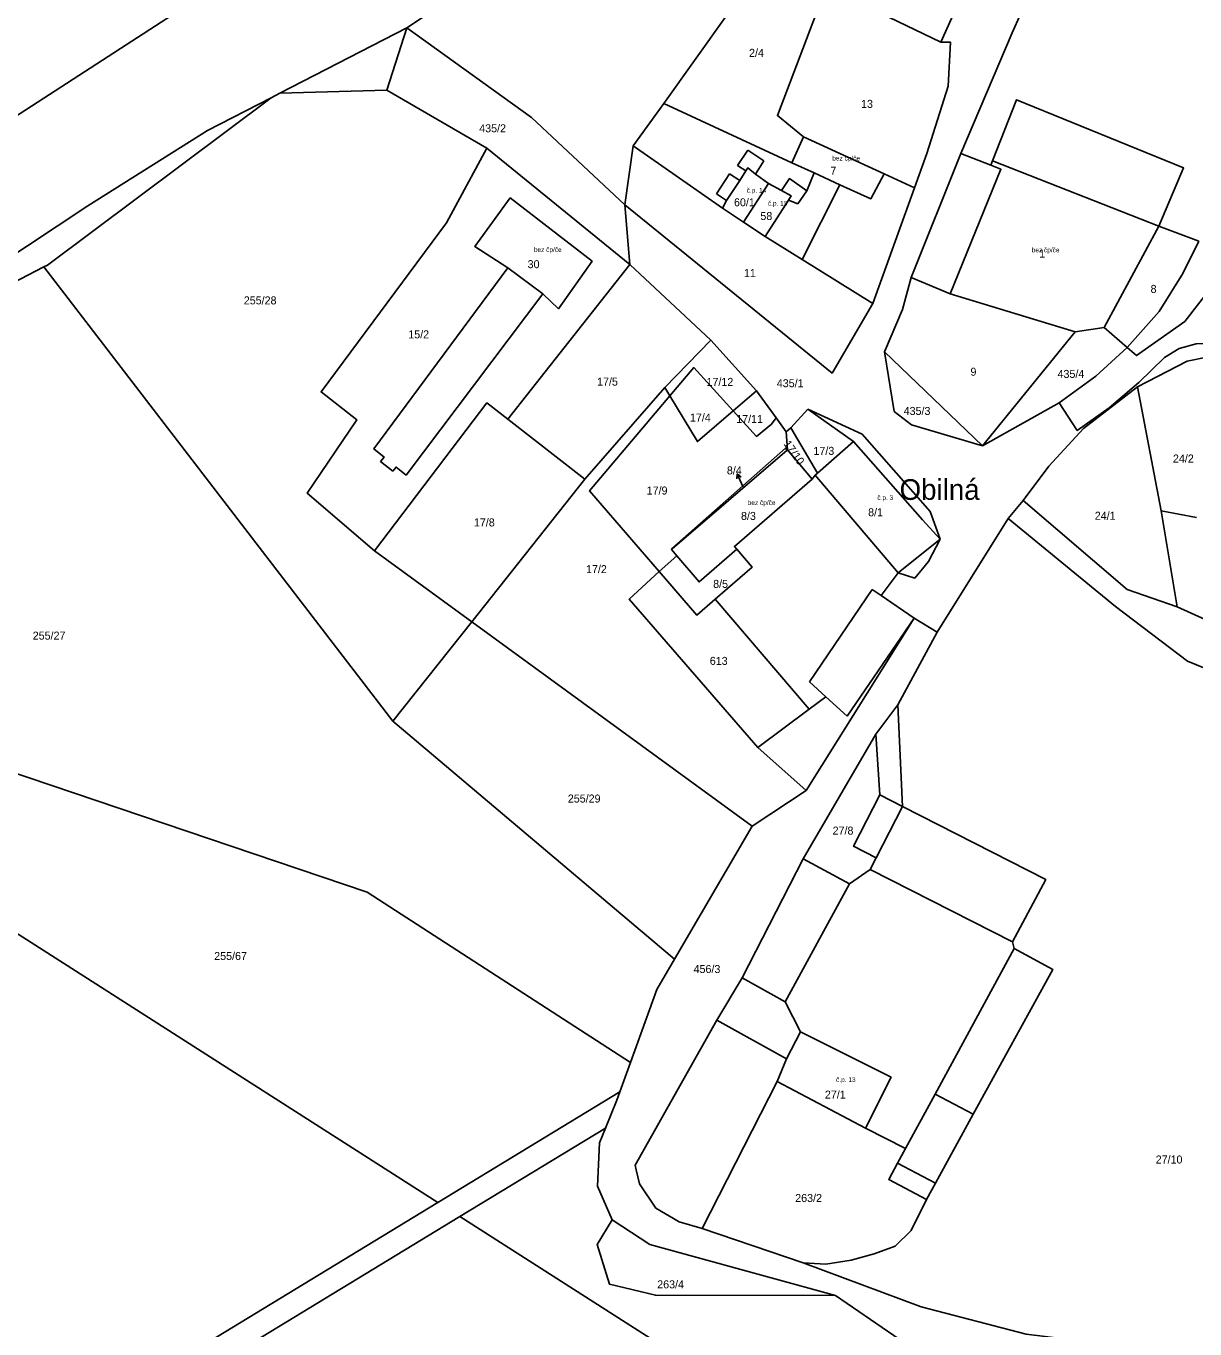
# Model space of a CAD drawing. Extents: x -887272 to -877616, y -1026687 to -1019819.
# Drawn here: x -880738 to -880489.6, y -1021447 to -1021170.2 of the extents above; entities that cross this region are included whole.
import ezdxf

# ---------------------------------------------------------------- set-up
doc = ezdxf.new("R2010")
doc.units = 0
for name, color, linetype in [('Definiční body', 7, 'Continuous'), ('Hranice parcel', 7, 'Continuous'), ('Parcelní čísla', 7, 'Continuous'), ('Polygon budovy', 7, 'Continuous'), ('Pop  PČ popisy', 7, 'Continuous'), ('Vnitřní kresba', 7, 'Continuous')]:
    doc.layers.add(name, color=color, linetype=linetype)

msp = doc.modelspace()

# ---------------------------------------------------------------- linework, layer by layer
at = {"layer": 'Hranice parcel'}
for p, q in [((-880602.77, -1021134.34), (-880657.13, -1021170.56)), ((-880661.35, -1021183.81), (-880657.13, -1021170.56)), ((-880684.13, -1021184.49), (-880685.95, -1021185.43)), ((-880661.35, -1021183.81), (-880684.13, -1021184.49)), ((-880640.11, -1021196.16), (-880661.35, -1021183.81)), ((-880602.45, -1021186.68), (-880609.03, -1021195.67)), ((-880575.27, -1021199.23), (-880602.45, -1021186.68)), ((-880610.78, -1021208.19), (-880609.03, -1021195.67)), ((-880572.81, -1021193.74), (-880575.27, -1021199.23)), ((-880609.7, -1021220.83), (-880640.11, -1021196.16)), ((-880539.35, -1021197.25), (-880549.94, -1021223.64)), ((-880575.27, -1021199.23), (-880570.51, -1021201.41)), ((-880558.09, -1021229.15), (-880549.21, -1021204.6)), ((-880610.78, -1021208.19), (-880609.7, -1021220.83)), ((-880508.88, -1021234.25), (-880497.26, -1021212.75)), ((-880497.26, -1021212.75), (-880488.78, -1021215.92)), ((-880635.66, -1021253.7), (-880609.7, -1021220.83)), ((-880592.5, -1021236.92), (-880609.7, -1021220.83)), ((-880573.11, -1021219.79), (-880558.09, -1021229.15)), ((-880660.06, -1021317.87), (-880734.24, -1021221.36)), ((-880515.07, -1021235.18), (-880508.88, -1021234.25)), ((-880508.88, -1021234.25), (-880503.97, -1021238.53)), ((-880602.26, -1021246.99), (-880592.5, -1021236.92)), ((-880592.5, -1021236.92), (-880582.78, -1021247.68)), ((-880534.73, -1021259.38), (-880515.07, -1021235.18)), ((-880555.55, -1021239.39), (-880534.73, -1021259.38)), ((-880553.51, -1021252.07), (-880555.55, -1021239.39)), ((-880602.26, -1021246.99), (-880619.24, -1021266.45)), ((-880601.19, -1021248.78), (-880602.26, -1021246.99)), ((-880582.78, -1021247.68), (-880587.74, -1021251.95)), ((-880582.78, -1021247.68), (-880578.62, -1021253.43)), ((-880496.75, -1021273.23), (-880501.78, -1021246.86)), ((-880518.44, -1021250.25), (-880534.73, -1021259.38)), ((-880635.66, -1021253.7), (-880619.24, -1021266.45)), ((-880578.62, -1021253.43), (-880576.45, -1021256.43)), ((-880571.85, -1021251.6), (-880575.52, -1021255.6)), ((-880549.81, -1021254.92), (-880553.51, -1021252.07)), ((-880576.45, -1021256.43), (-880575.52, -1021255.6)), ((-880576.21, -1021260.26), (-880576.45, -1021256.43)), ((-880575.52, -1021255.6), (-880569.82, -1021265.22)), ((-880534.73, -1021259.38), (-880549.81, -1021254.92)), ((-880576.27, -1021260.3), (-880600.72, -1021281.3)), ((-880576.21, -1021260.26), (-880576.27, -1021260.3)), ((-880570.93, -1021266.47), (-880576.21, -1021260.26)), ((-880619.24, -1021266.45), (-880643.31, -1021296.77)), ((-880570.93, -1021266.47), (-880587.47, -1021280.76)), ((-880526.13, -1021271.04), (-880529.31, -1021274.86)), ((-880493.37, -1021293.62), (-880496.75, -1021273.23)), ((-880496.75, -1021273.23), (-880489.23, -1021274.65)), ((-880529.31, -1021274.86), (-880544.36, -1021298.96)), ((-880663.97, -1021281.71), (-880643.31, -1021296.77)), ((-880587.47, -1021280.76), (-880586.95, -1021281.37)), ((-880599.75, -1021282.74), (-880603.45, -1021286.13)), ((-880660.06, -1021317.87), (-880643.31, -1021296.77)), ((-880643.31, -1021296.77), (-880583.69, -1021340.23)), ((-880572.25, -1021332.66), (-880549.24, -1021296.04)), ((-880544.36, -1021298.96), (-880549.24, -1021296.04)), ((-880544.36, -1021298.96), (-880552.77, -1021314.46)), ((-880551.77, -1021336.02), (-880552.77, -1021314.46)), ((-880600.19, -1021368.5), (-880660.06, -1021317.87)), ((-880582.47, -1021323.52), (-880572.25, -1021332.66)), ((-880583.69, -1021340.23), (-880572.25, -1021332.66)), ((-880600.19, -1021368.5), (-880583.69, -1021340.23)), ((-880609.55, -1021390.4), (-880611.8, -1021396.64)), ((-880611.8, -1021396.64), (-880650.52, -1021420.19)), ((-880645.83, -1021423.18), (-880614.91, -1021404.39))]:
    msp.add_line(p, q, dxfattribs=at)
for points in [[(-880602.45, -1021186.68), (-880589.43, -1021168.38), (-880587.64, -1021162.87), (-880580.4, -1021148.8)], [(-880572.81, -1021193.74), (-880578.34, -1021189.21), (-880566, -1021156.7)], [(-880566, -1021156.7), (-880560.4, -1021159.2), (-880562.3, -1021164.6), (-880556.46, -1021167.45), (-880543.6, -1021173.6)], [(-880543.6, -1021173.6), (-880540.67, -1021167.18), (-880535.26, -1021161.4), (-880525.8, -1021164)], [(-880699.29, -1021162.79), (-880808.35, -1021233.5), (-880873.35, -1021274.78), (-880941.52, -1021318.31), (-881007.7, -1021360.64), (-881104.49, -1021422.63)], [(-880525.8, -1021164), (-880526.67, -1021167.7), (-880528.44, -1021171.66), (-880539.35, -1021197.25)], [(-880657.13, -1021170.56), (-880630.62, -1021189.66), (-880610.78, -1021208.19)], [(-880549.21, -1021204.6), (-880546.57, -1021197.29), (-880542.08, -1021183), (-880541.56, -1021173.61), (-880543.6, -1021173.6)], [(-880685.95, -1021185.43), (-880733.48, -1021220.97), (-880734.24, -1021221.36)], [(-880497.26, -1021212.75), (-880492.02, -1021200.33), (-880527.51, -1021185.87), (-880532.64, -1021198.87), (-880532.99, -1021199.76), (-880539.35, -1021197.25)], [(-880518.44, -1021250.25), (-880514.62, -1021256.12), (-880507.85, -1021251.3), (-880501.52, -1021245.91), (-880496.1, -1021240.64), (-880492.92, -1021238.71), (-880489.34, -1021237.69), (-880485.62, -1021237.66), (-880482.02, -1021238.6), (-880479.01, -1021240.25), (-880471.89, -1021236.03), (-880478.16, -1021217.09), (-880475.5, -1021210.72), (-880473.54, -1021204.78), (-880469.31, -1021188.85)], [(-880473.96, -1021187.71), (-880477.55, -1021197.73), (-880482.75, -1021218.18), (-880486.35, -1021226.03), (-880491.71, -1021232.97), (-880502.05, -1021240.2), (-880503.97, -1021238.53)], [(-880609.03, -1021195.67), (-880590.04, -1021208.86), (-880585.54, -1021211.87)], [(-880549.21, -1021204.6), (-880555.68, -1021201.63), (-880572.81, -1021193.74)], [(-880640.11, -1021196.16), (-880648.7, -1021212.02), (-880675.32, -1021247.93), (-880667.72, -1021253.89), (-880678.26, -1021269.48), (-880663.97, -1021281.71)], [(-880570.51, -1021201.41), (-880572.08, -1021205.18), (-880575.78, -1021202.6), (-880577.44, -1021205.12), (-880580.21, -1021203.62), (-880585.54, -1021211.87)], [(-880570.51, -1021201.41), (-880565.05, -1021203.91), (-880573.11, -1021219.79)], [(-880660.1, -1021264.79), (-880659.38, -1021263.9), (-880657.25, -1021265.62), (-880628.23, -1021227.08), (-880624.89, -1021230.28), (-880617.72, -1021220.17), (-880635.14, -1021206.73), (-880642.65, -1021217.05), (-880635.61, -1021221.58), (-880664.11, -1021260.06), (-880661.96, -1021261.8), (-880662.68, -1021262.69), (-880660.1, -1021264.79)], [(-880610.78, -1021208.19), (-880566.73, -1021243.92), (-880558.09, -1021229.15)], [(-880585.54, -1021211.87), (-880580.91, -1021214.93), (-880573.11, -1021219.79)], [(-880503.97, -1021238.53), (-880497.17, -1021230.88), (-880492.15, -1021222.79), (-880488.78, -1021215.92)], [(-880734.24, -1021221.36), (-880777.81, -1021244), (-880800.04, -1021257.88), (-880834.2, -1021278.73), (-880852.86, -1021290.89)], [(-880549.94, -1021223.64), (-880551.76, -1021230.43), (-880555.55, -1021239.39)], [(-880549.94, -1021223.64), (-880541.6, -1021227.12), (-880515.07, -1021235.18)], [(-880503.97, -1021238.53), (-880510.64, -1021244.58), (-880518.44, -1021250.25)], [(-880587.74, -1021251.95), (-880596.12, -1021242.78), (-880601.19, -1021248.78)], [(-880474.8, -1021254.79), (-880474.36, -1021244.16), (-880474.25, -1021241.54), (-880476.39, -1021241.38), (-880487.08, -1021240.58), (-880491.24, -1021241.37), (-880501.78, -1021246.86)], [(-880501.78, -1021246.86), (-880513.29, -1021255.74), (-880520.64, -1021263.73), (-880526.13, -1021271.04)], [(-880663.97, -1021281.71), (-880640.08, -1021250.27), (-880635.66, -1021253.7)], [(-880603.45, -1021286.13), (-880618.25, -1021268.95), (-880601.19, -1021248.78)], [(-880601.19, -1021248.78), (-880595.35, -1021258.5), (-880587.74, -1021251.95)], [(-880578.62, -1021253.43), (-880579.62, -1021254.79), (-880582.78, -1021257.38), (-880587.74, -1021251.95)], [(-880549.24, -1021296.04), (-880556.3, -1021291.23), (-880552.71, -1021286.35), (-880549.16, -1021287.48), (-880546.25, -1021284), (-880543.76, -1021279.24), (-880545.84, -1021273.35), (-880560.34, -1021256.93), (-880571.85, -1021251.6)], [(-880571.85, -1021251.6), (-880562.14, -1021258.44), (-880569.82, -1021265.22)], [(-880576.27, -1021260.3), (-880576.61, -1021259.91), (-880600.81, -1021281.19), (-880600.72, -1021281.3)], [(-880569.82, -1021265.22), (-880570.32, -1021265.66), (-880570.93, -1021266.47)], [(-880526.13, -1021271.04), (-880504.01, -1021289.9), (-880493.37, -1021293.62)], [(-880529.31, -1021274.86), (-880506.49, -1021293.52), (-880491.17, -1021305.16), (-880467.02, -1021315.01), (-880447.92, -1021320.85), (-880429.84, -1021330.36), (-880427.85, -1021339.96)], [(-880600.72, -1021281.3), (-880600.87, -1021281.44), (-880599.75, -1021282.74)], [(-880586.95, -1021281.37), (-880594.98, -1021288.3), (-880599.75, -1021282.74)], [(-880591.58, -1021291.98), (-880583.68, -1021285.16), (-880586.95, -1021281.37)], [(-880582.47, -1021323.52), (-880609.82, -1021291.97), (-880603.45, -1021286.13)], [(-880591.58, -1021291.98), (-880595.49, -1021295.36), (-880603.45, -1021286.13)], [(-880852.86, -1021290.89), (-880665.52, -1021354.25), (-880609.55, -1021390.4)], [(-880650.52, -1021420.19), (-880751.74, -1021355.5), (-880852.86, -1021290.89)], [(-880591.58, -1021291.98), (-880571.6, -1021315.37), (-880582.47, -1021323.52)], [(-880493.37, -1021293.62), (-880484.47, -1021297.65), (-880464.66, -1021305.36)], [(-880552.77, -1021314.46), (-880557.4, -1021320.65), (-880572.87, -1021347.16)], [(-880551.77, -1021336.02), (-880556.59, -1021333.55), (-880562.16, -1021344.48), (-880557.37, -1021346.94), (-880558.66, -1021349.45), (-880562.99, -1021352.49), (-880572.87, -1021347.16)], [(-880546.66, -1021419.56), (-880544.76, -1021416.1), (-880536.71, -1021401.44), (-880519.81, -1021370.66), (-880528.01, -1021366.19), (-880528.37, -1021364.81), (-880521.3, -1021351.55), (-880551.77, -1021336.02)], [(-880572.87, -1021347.16), (-880585.84, -1021372.47), (-880591.22, -1021381.45)], [(-880609.55, -1021390.4), (-880608, -1021386.1), (-880603.94, -1021374.93), (-880600.19, -1021368.5)], [(-880591.22, -1021381.45), (-880608.58, -1021412.27), (-880608.35, -1021413.24), (-880607.63, -1021416.21), (-880604.16, -1021421.37), (-880599.2, -1021424.29), (-880594.31, -1021425.69), (-880572.86, -1021432.99)], [(-880591.22, -1021381.45), (-880576.42, -1021389.62), (-880578.36, -1021394.48), (-880559.6, -1021404.38), (-880551.1, -1021408.71), (-880552.81, -1021411.85), (-880554.69, -1021415.32), (-880546.66, -1021419.56)], [(-880614.91, -1021404.39), (-880612.44, -1021398.43), (-880611.8, -1021396.64)], [(-880614.91, -1021404.39), (-880616.19, -1021407.47), (-880616.55, -1021416.74), (-880613.47, -1021423.85)], [(-880650.52, -1021420.19), (-880734.5, -1021471.26), (-880791.06, -1021515.8)], [(-880546.66, -1021419.56), (-880549.89, -1021426.1), (-880553.31, -1021429.43), (-880557.81, -1021431.11), (-880562.65, -1021432.4), (-880568.03, -1021433.26), (-880572.86, -1021432.99)], [(-880872.75, -1021653.59), (-880853.95, -1021571.88), (-880731.4, -1021475.19), (-880645.83, -1021423.18)], [(-880645.83, -1021423.18), (-880556.09, -1021480.53), (-880466.28, -1021537.91)], [(-880613.47, -1021423.85), (-880616.65, -1021429.12), (-880614.04, -1021437.55), (-880604.28, -1021439.9), (-880566, -1021439.93)], [(-880566, -1021439.93), (-880605.48, -1021429.1), (-880613.47, -1021423.85)], [(-880572.86, -1021432.99), (-880547.77, -1021442.37), (-880525.48, -1021448.12), (-880467.26, -1021455.29)], [(-880566, -1021439.93), (-880548.61, -1021451.85), (-880527.16, -1021455.82), (-880478.38, -1021460.24)]]:
    msp.add_lwpolyline(points, dxfattribs=at)
at = {"layer": 'Polygon budovy'}
for points in [[(-880575.27, -1021199.23), (-880570.51, -1021201.41), (-880565.05, -1021203.91), (-880558.49, -1021206.91), (-880555.68, -1021201.63), (-880572.81, -1021193.74)], [(-880582.98, -1021201.65), (-880584.66, -1021200.35), (-880585.06, -1021200.96), (-880586.36, -1021202.98), (-880589.13, -1021207.27), (-880590.04, -1021208.86), (-880585.54, -1021211.87), (-880580.21, -1021203.62)], [(-880508.88, -1021234.25), (-880497.26, -1021212.75), (-880532.64, -1021198.87), (-880532.99, -1021199.76), (-880530.85, -1021200.61), (-880541.6, -1021227.12), (-880515.07, -1021235.18)], [(-880585.54, -1021211.87), (-880580.91, -1021214.93), (-880576.02, -1021207.19), (-880575.42, -1021206.24), (-880577.44, -1021205.12), (-880580.21, -1021203.62)], [(-880642.65, -1021217.05), (-880635.61, -1021221.58), (-880628.23, -1021227.08), (-880624.89, -1021230.28), (-880617.72, -1021220.17), (-880635.14, -1021206.73)], [(-880570.32, -1021265.66), (-880552.71, -1021286.35), (-880543.76, -1021279.24), (-880547.53, -1021275.14), (-880562.14, -1021258.44), (-880569.82, -1021265.22)], [(-880576.21, -1021260.26), (-880576.27, -1021260.3), (-880600.72, -1021281.3), (-880600.87, -1021281.44), (-880599.75, -1021282.74), (-880594.98, -1021288.3), (-880586.95, -1021281.37), (-880587.47, -1021280.76), (-880570.93, -1021266.47)], [(-880578.36, -1021394.48), (-880559.6, -1021404.38), (-880554.18, -1021393.55), (-880573.42, -1021383.9), (-880576.42, -1021389.62)]]:
    msp.add_lwpolyline(points, close=True, dxfattribs=at)
at = {"layer": 'Pop  PČ popisy'}
for p, q in [((-880586.89, -1021265.31), (-880586.94, -1021266.43)), ((-880585.67, -1021268.05), (-880586.89, -1021265.31)), ((-880586.89, -1021265.31), (-880586.03, -1021266.02)), ((-880585.63, -1021268.14), (-880585.67, -1021268.05))]:
    msp.add_line(p, q, dxfattribs=at)
at = {"layer": 'Vnitřní kresba'}
for p, q in [((-880657.13, -1021170.56), (-880684.13, -1021184.49)), ((-880685.95, -1021185.43), (-880699.48, -1021192.4)), ((-880699.48, -1021192.4), (-880724.89, -1021208.38)), ((-880586.84, -1021199.82), (-880584.65, -1021196.55)), ((-880584.65, -1021196.55), (-880581.26, -1021198.85)), ((-880586.84, -1021199.82), (-880585.06, -1021200.96)), ((-880586.36, -1021202.98), (-880585.06, -1021200.96)), ((-880585.06, -1021200.96), (-880584.66, -1021200.35)), ((-880584.66, -1021200.35), (-880582.98, -1021201.65)), ((-880582.98, -1021201.65), (-880581.26, -1021198.85)), ((-880541.6, -1021227.12), (-880530.85, -1021200.61)), ((-880532.99, -1021199.76), (-880530.85, -1021200.61)), ((-880532.64, -1021198.87), (-880497.26, -1021212.75)), ((-880591.31, -1021205.87), (-880588.54, -1021201.58)), ((-880589.13, -1021207.27), (-880586.36, -1021202.98)), ((-880588.54, -1021201.58), (-880586.36, -1021202.98)), ((-880582.98, -1021201.65), (-880580.21, -1021203.62)), ((-880565.05, -1021203.91), (-880558.49, -1021206.91)), ((-880558.49, -1021206.91), (-880555.68, -1021201.63)), ((-880591.31, -1021205.87), (-880589.13, -1021207.27)), ((-880577.44, -1021205.12), (-880575.42, -1021206.24)), ((-880576.02, -1021207.19), (-880575.42, -1021206.24)), ((-880574, -1021207.95), (-880572.08, -1021205.18)), ((-880724.89, -1021208.38), (-880758.2, -1021230.44)), ((-880590.04, -1021208.86), (-880589.13, -1021207.27)), ((-880580.91, -1021214.93), (-880576.02, -1021207.19)), ((-880576.02, -1021207.19), (-880574, -1021207.95)), ((-880635.61, -1021221.58), (-880628.23, -1021227.08)), ((-880562.14, -1021258.44), (-880547.53, -1021275.14)), ((-880570.32, -1021265.66), (-880552.71, -1021286.35)), ((-880547.53, -1021275.14), (-880543.76, -1021279.24)), ((-880552.71, -1021286.35), (-880543.76, -1021279.24)), ((-880571.55, -1021309.52), (-880558.2, -1021289.93)), ((-880558.2, -1021289.93), (-880556.3, -1021291.23)), ((-880563.48, -1021316.87), (-880549.24, -1021296.04)), ((-880571.55, -1021309.52), (-880568.05, -1021312.71)), ((-880571.6, -1021315.37), (-880568.05, -1021312.71)), ((-880568.05, -1021312.71), (-880563.48, -1021316.87)), ((-880557.4, -1021320.65), (-880556.59, -1021333.55)), ((-880557.37, -1021346.94), (-880551.77, -1021336.02)), ((-880558.66, -1021349.45), (-880528.37, -1021364.81)), ((-880576.66, -1021377.55), (-880562.99, -1021352.49)), ((-880544.83, -1021397.15), (-880528.01, -1021366.19)), ((-880585.84, -1021372.47), (-880576.66, -1021377.55)), ((-880576.66, -1021377.55), (-880573.42, -1021383.9)), ((-880576.42, -1021389.62), (-880573.42, -1021383.9)), ((-880573.42, -1021383.9), (-880554.18, -1021393.55)), ((-880594.31, -1021425.69), (-880578.36, -1021394.48)), ((-880559.6, -1021404.38), (-880554.18, -1021393.55)), ((-880551.1, -1021408.71), (-880544.83, -1021397.15)), ((-880544.83, -1021397.15), (-880536.71, -1021401.44)), ((-880552.81, -1021411.85), (-880544.76, -1021416.1))]:
    msp.add_line(p, q, dxfattribs=at)

# ---------------------------------------------------------------- texts
at = {"layer": 'Definiční body'}
for s, p in [('bez čp/če', (-880566.68, -1021198.77)), ('č.p. 14', (-880584.87, -1021205.6)), ('č.p. 15', (-880580.37, -1021208.36)), ('bez čp/če', (-880630.1, -1021218.2)), ('bez čp/če', (-880524.29, -1021218.27)), ('č.p. 3', (-880557.1, -1021270.9)), ('bez čp/če', (-880584.65, -1021271.96)), ('č.p. 13', (-880565.87, -1021394.57))]:
    msp.add_text(s, height=1, dxfattribs=at).set_placement(p)
at = {"layer": 'Parcelní čísla'}
for s, p in [('2/4', (-880584.37, -1021176.74)), ('13', (-880560.56, -1021187.58)), ('435/2', (-880641.72, -1021192.77)), ('7', (-880567.08, -1021201.78)), ('60/1', (-880587.57, -1021208.49)), ('58', (-880581.96, -1021211.41)), ('1', (-880522.71, -1021219.41)), ('30', (-880631.43, -1021221.65)), ('11', (-880585.47, -1021223.54)), ('8', (-880499.02, -1021226.9)), ('255/28', (-880691.76, -1021229.34)), ('15/2', (-880656.8, -1021236.56)), ('9', (-880537.31, -1021244.5)), ('17/5', (-880616.67, -1021246.6)), ('17/12', (-880593.41, -1021246.66)), ('435/1', (-880578.47, -1021246.94)), ('435/4', (-880518.8, -1021244.96)), ('435/3', (-880551.51, -1021252.83)), ('17/4', (-880596.93, -1021254.23)), ('17/11', (-880587.1, -1021254.54)), ('17/3', (-880570.68, -1021261.31)), ('24/2', (-880494.27, -1021262.94)), ('8/4', (-880589.08, -1021265.47)), ('17/9', (-880606.13, -1021269.74)), ('8/3', (-880586.08, -1021275.14)), ('8/1', (-880559.06, -1021274.36)), ('24/1', (-880510.89, -1021275.1)), ('17/8', (-880642.85, -1021276.52)), ('17/2', (-880619.02, -1021286.45)), ('8/5', (-880592, -1021289.58)), ('255/27', (-880736.62, -1021300.57)), ('613', (-880592.71, -1021305.94)), ('255/29', (-880622.89, -1021335.19)), ('27/8', (-880566.61, -1021342)), ('255/67', (-880698.05, -1021368.65)), ('456/3', (-880596.16, -1021371.42)), ('27/1', (-880568.25, -1021398.1)), ('27/10', (-880497.94, -1021411.89)), ('263/2', (-880574.56, -1021420.07)), ('263/4', (-880603.89, -1021438.42))]:
    msp.add_text(s, height=1.7, dxfattribs=at).set_placement(p)
msp.add_text('17/10', height=1.7, rotation=305, dxfattribs=at).set_placement((-880577.12, -1021258.97))
at = {"layer": 'Pop  PČ popisy'}
msp.add_text('Obilná', height=4.4, dxfattribs=at).set_placement((-880552.37, -1021270.88))

doc.saveas('drawing.dxf')
